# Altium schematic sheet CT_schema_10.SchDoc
size 147 x 119 mm
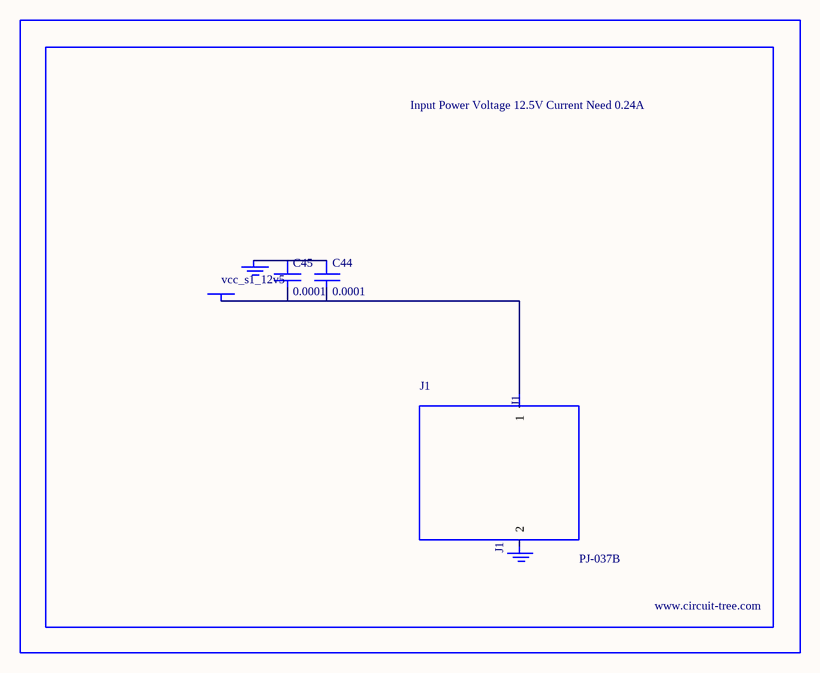
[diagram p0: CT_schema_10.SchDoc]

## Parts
BORDER9  (no value)
C44  0.0001  [EXV-9H]
C45  0.0001  [EXV-9H]
GND_INSTANCE_9_0  (no value)
GND_INSTANCE_9_1  (no value)
J1  PJ-037B  [PJ-037B_PACKAGE]
POWER_INSTANCE_9_0  vcc_s1_12v5

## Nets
NetC44_1: C44.1 C45.1 GND_INSTANCE_9_0.0(GND)
NetC44_2: C44.2 C45.2 J1.1 POWER_INSTANCE_9_0.0(PWR)

Not connected (* = marked no-connect by the designer): GND_INSTANCE_9_1 0(GND); J1 2

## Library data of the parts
BORDER9 = BORDER_PAGE9
C44 C45 = EDK107M035A9HAA
GND_INSTANCE_9_0 GND_INSTANCE_9_1 = GND
POWER_INSTANCE_9_0 = PWR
